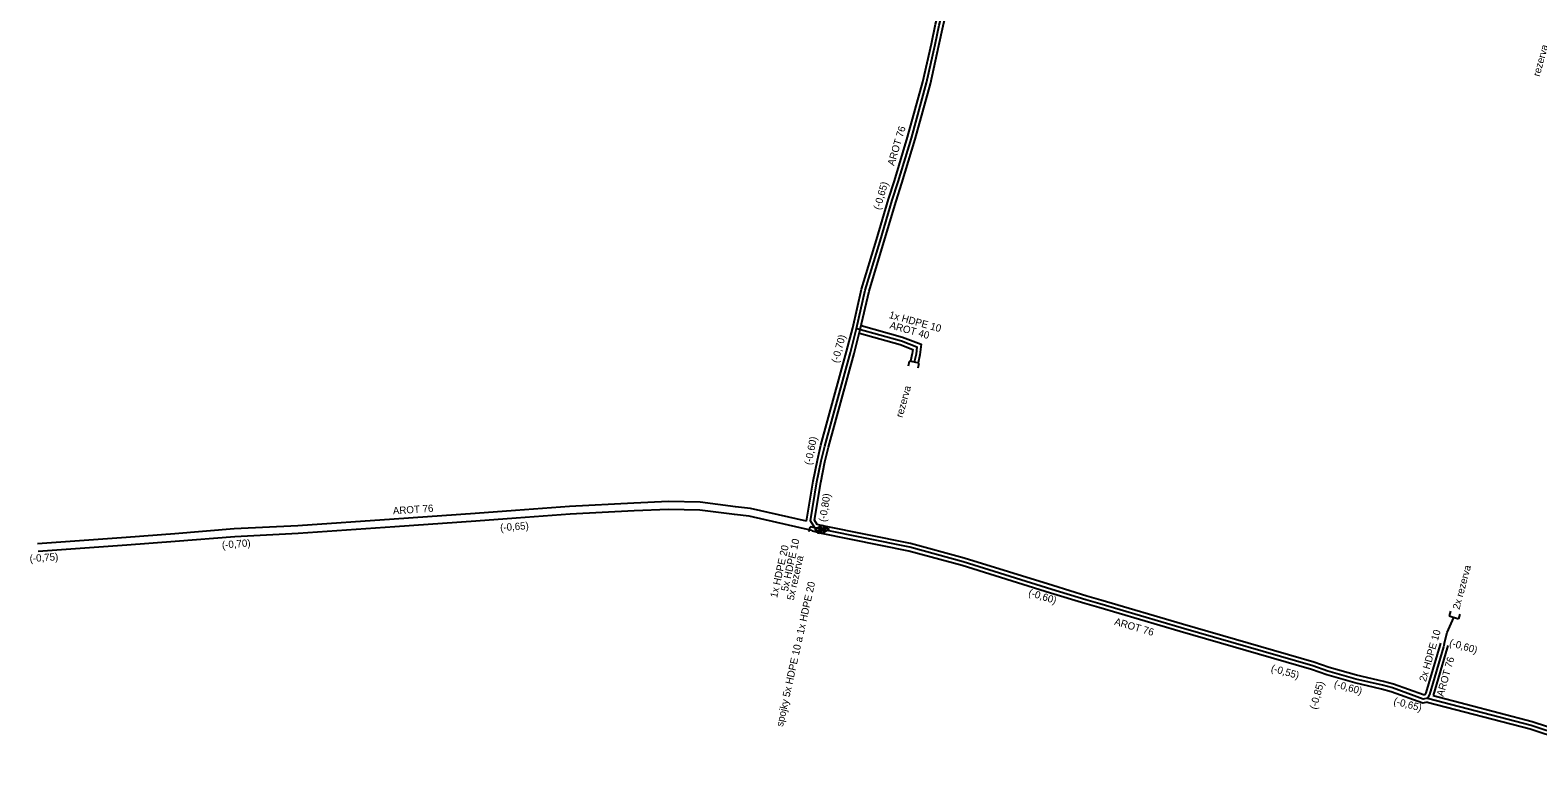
# Model space of a CAD drawing. Extents: x -651943 to -618711, y -1138561 to -1100552.
# Drawn here: x -635177.4 to -635021.9, y -1115478.4 to -1115401.6 of the extents above; entities that cross this region are included whole.
import ezdxf

# ---------------------------------------------------------------- set-up
doc = ezdxf.new("R2010")
doc.units = 0
for name, color, linetype in [('KT optika', 7, 'Continuous'), ('KT trasa', 7, 'Continuous'), ('KT zařízení', 7, 'Continuous')]:
    doc.layers.add(name, color=color, linetype=linetype)

# ---------------------------------------------------------------- blocks, each defined once
blk = doc.blocks.new('TVSPO_1')
at = {"layer": 'KT zařízení'}
for p, q in [((-0.074, 0.002), (0, 0.044)), ((-0.001, -0.041), (-0.074, 0.002)), ((-0.035, 0), (0, 0.02)), ((0.073, 0.001), (-0.001, -0.041)), ((0, 0.044), (0.073, 0.001)), ((0, 0.02), (0.035, 0)), ((0.035, 0), (0, -0.02)), ((0, -0.02), (-0.035, 0))]:
    blk.add_line(p, q, dxfattribs=at)
blk = doc.blocks.new('TVREZ')
at = {"layer": 'KT zařízení'}
for p, q in [((-0.05, 0.05), (0, 0.05)), ((0, -0.05), (0, 0.05)), ((-0.05, -0.05), (0, -0.05))]:
    blk.add_line(p, q, dxfattribs=at)

msp = doc.modelspace()

# ---------------------------------------------------------------- linework, layer by layer
at = {"layer": 'KT optika'}
for points in [[(-635096.92, -1115452.23), (-635096.27, -1115448.2), (-635095.83, -1115446.04), (-635095.46, -1115444.52), (-635092.82, -1115434.86), (-635092.18, -1115432.4), (-635091.28, -1115428.45), (-635089.75, -1115423.38), (-635088.5, -1115419.16), (-635087.89, -1115417.28), (-635086.53, -1115412.77), (-635084.96, -1115407.07), (-635084.08, -1115403.13), (-635083.65, -1115401.11), (-635083.25, -1115399.55), (-635082.29, -1115396.3), (-635082.04, -1115395.65), (-635081.23, -1115392.99), (-635079.5, -1115386.84), (-635079.42, -1115385.67), (-635078.97, -1115383.87), (-635077.85, -1115380.09)], [(-635092.18, -1115432.4), (-635092.03, -1115432.41), (-635087.56, -1115433.65), (-635085.96, -1115434.28), (-635086.04, -1115435.04), (-635086.23, -1115435.85)], [(-635031.6, -1115464.94), (-635031.68, -1115465.2), (-635033.11, -1115470.12), (-635033.33, -1115470.49), (-635033.77, -1115470.59), (-635036.93, -1115469.45), (-635037.96, -1115469.17), (-635040.72, -1115468.53), (-635043.58, -1115467.73), (-635045.15, -1115467.18), (-635058.7, -1115463.25), (-635067.1, -1115460.78), (-635068.54, -1115460.37), (-635072.06, -1115459.28), (-635081.19, -1115456.43), (-635086.7, -1115454.95), (-635095.73, -1115453.12), (-635096.48, -1115452.95), (-635096.92, -1115452.23)], [(-635031.6, -1115464.94), (-635031.29, -1115463.74), (-635030.61, -1115462.17)], [(-635033.33, -1115470.49), (-635022.63, -1115473.28), (-635012.93, -1115476.46), (-635007.19, -1115478.02), (-635006.94, -1115477.98), (-635006.59, -1115477.22), (-635005.3, -1115473.3), (-635005.1, -1115472.7)]]:
    msp.add_lwpolyline(points, dxfattribs=at)
at = {"layer": 'KT trasa'}
for points in [[(-635096.92, -1115452.23), (-635096.27, -1115448.2), (-635095.83, -1115446.04), (-635095.46, -1115444.52), (-635092.82, -1115434.86), (-635092.18, -1115432.4), (-635091.28, -1115428.45), (-635089.75, -1115423.38), (-635088.5, -1115419.16), (-635087.89, -1115417.28), (-635086.53, -1115412.77), (-635084.96, -1115407.07), (-635084.08, -1115403.13), (-635083.65, -1115401.11), (-635083.25, -1115399.55), (-635082.29, -1115396.3), (-635082.04, -1115395.65), (-635081.23, -1115392.99), (-635079.5, -1115386.84), (-635079.42, -1115385.67), (-635078.97, -1115383.87), (-635077.85, -1115380.09)], [(-635092.18, -1115432.4), (-635092.03, -1115432.41), (-635087.56, -1115433.65), (-635085.96, -1115434.28), (-635086.04, -1115435.04), (-635086.23, -1115435.85)], [(-635031.6, -1115464.94), (-635031.68, -1115465.2), (-635033.11, -1115470.12), (-635033.33, -1115470.49), (-635033.77, -1115470.59), (-635036.93, -1115469.45), (-635037.96, -1115469.17), (-635040.72, -1115468.53), (-635043.58, -1115467.73), (-635045.15, -1115467.18), (-635058.7, -1115463.25), (-635067.1, -1115460.78), (-635068.54, -1115460.37), (-635072.06, -1115459.28), (-635081.19, -1115456.43), (-635086.7, -1115454.95), (-635095.73, -1115453.12), (-635096.48, -1115452.95), (-635096.92, -1115452.23)], [(-635031.6, -1115464.94), (-635031.29, -1115463.74), (-635030.61, -1115462.17)], [(-635033.33, -1115470.49), (-635022.63, -1115473.28), (-635012.93, -1115476.46), (-635007.19, -1115478.02), (-635006.94, -1115477.98), (-635006.59, -1115477.22), (-635005.3, -1115473.3), (-635005.1, -1115472.7)]]:
    msp.add_lwpolyline(points, dxfattribs=at)
at = {"layer": 'KT zařízení'}
msp.add_line((-635095.52, -1115453.15), (-635095.73, -1115453.12), dxfattribs=at)
for points in [[(-635097.33, -1115452.27), (-635096.66, -1115448.13), (-635096.22, -1115445.95), (-635095.85, -1115444.42), (-635093.21, -1115434.76), (-635092.57, -1115432.31), (-635091.67, -1115428.35), (-635090.13, -1115423.26), (-635088.88, -1115419.05), (-635088.27, -1115417.16), (-635086.92, -1115412.66), (-635085.35, -1115406.97), (-635084.47, -1115403.05), (-635084.04, -1115401.02), (-635083.63, -1115399.45), (-635082.67, -1115396.17), (-635082.42, -1115395.52), (-635081.61, -1115392.88), (-635079.9, -1115386.77), (-635079.82, -1115385.6), (-635079.36, -1115383.77), (-635078.35, -1115380.38)], [(-635096.5, -1115452.15), (-635095.88, -1115448.27), (-635095.44, -1115446.13), (-635095.07, -1115444.62), (-635092.44, -1115434.97), (-635091.8, -1115432.5), (-635090.89, -1115428.55), (-635089.37, -1115423.49), (-635088.11, -1115419.28), (-635087.51, -1115417.4), (-635086.15, -1115412.88), (-635084.57, -1115407.16), (-635083.69, -1115403.22), (-635083.26, -1115401.2), (-635082.86, -1115399.66), (-635081.91, -1115396.42), (-635081.66, -1115395.78), (-635080.84, -1115393.1), (-635079.11, -1115386.91), (-635079.03, -1115385.73), (-635078.58, -1115383.98), (-635077.47, -1115380.22)], [(-635091.89, -1115432.86), (-635087.69, -1115434.03), (-635086.39, -1115434.54), (-635086.44, -1115434.97), (-635086.62, -1115435.76)], [(-635091.7, -1115432.09), (-635087.43, -1115433.27), (-635085.53, -1115434.02), (-635085.65, -1115435.11), (-635085.84, -1115435.94)], [(-635097.33, -1115452.27), (-635103.1, -1115450.95), (-635104.65, -1115450.78), (-635108.29, -1115450.31), (-635111.58, -1115450.24), (-635115.15, -1115450.4), (-635121.76, -1115450.74), (-635127.33, -1115451.15), (-635131.5, -1115451.45), (-635139.84, -1115452.05), (-635149.78, -1115452.72), (-635156.35, -1115453.06), (-635162.48, -1115453.55), (-635167.49, -1115453.94), (-635176.63, -1115454.58)], [(-635096.79, -1115453.21), (-635103.24, -1115451.74), (-635104.75, -1115451.58), (-635108.35, -1115451.11), (-635111.57, -1115451.04), (-635115.12, -1115451.2), (-635121.71, -1115451.54), (-635127.27, -1115451.94), (-635131.44, -1115452.25), (-635139.78, -1115452.85), (-635149.74, -1115453.52), (-635156.29, -1115453.86), (-635162.42, -1115454.35), (-635167.43, -1115454.74), (-635176.57, -1115455.38)], [(-635033.34, -1115470.9), (-635033.8, -1115471.01), (-635037.05, -1115469.83), (-635038.06, -1115469.56), (-635040.82, -1115468.92), (-635043.7, -1115468.11), (-635045.27, -1115467.56), (-635058.81, -1115463.63), (-635067.21, -1115461.16), (-635068.65, -1115460.75), (-635072.18, -1115459.66), (-635081.3, -1115456.81), (-635086.79, -1115455.34), (-635095.81, -1115453.51), (-635096.73, -1115453.3), (-635096.79, -1115453.21)], [(-635031.98, -1115464.82), (-635032.06, -1115465.08), (-635033.48, -1115469.96), (-635033.59, -1115470.14), (-635033.74, -1115470.17), (-635036.81, -1115469.07), (-635037.86, -1115468.78), (-635040.62, -1115468.14), (-635043.46, -1115467.35), (-635045.03, -1115466.8), (-635058.59, -1115462.87), (-635066.99, -1115460.4), (-635068.43, -1115459.99), (-635071.94, -1115458.9), (-635081.08, -1115456.05), (-635086.61, -1115454.56), (-635095.65, -1115452.73), (-635096.23, -1115452.6), (-635096.5, -1115452.15)], [(-635031.22, -1115465.06), (-635031.3, -1115465.31), (-635032.73, -1115470.23)], [(-635032.73, -1115470.23), (-635022.52, -1115472.9), (-635012.82, -1115476.08), (-635007.21, -1115477.6), (-635006.96, -1115477.07), (-635005.68, -1115473.17), (-635005.48, -1115472.57)], [(-635033.34, -1115470.9), (-635022.74, -1115473.66), (-635013.05, -1115476.84), (-635007.31, -1115478.4)]]:
    msp.add_lwpolyline(points, dxfattribs=at)

# ---------------------------------------------------------------- block references
for p, xscale, yscale, rotation in [((-635086.23, -1115435.85), 9.999989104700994, 9.999989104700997, 78.294855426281), ((-635096.48, -1115452.95), 10.00002132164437, 10.000021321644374, 77.39068404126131), ((-635030.61, -1115462.17), 9.99999500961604, 9.99999500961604, -106.8298317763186)]:
    msp.add_blockref('TVREZ', p, dxfattribs=dict(at, xscale=xscale, yscale=yscale, rotation=rotation))
at = {"layer": 'KT zařízení', "xscale": 10, "yscale": 10}
msp.add_blockref('TVSPO_1', (-635095.73, -1115453.12), dxfattribs=at)

# ---------------------------------------------------------------- texts
at = {"layer": 'KT zařízení'}
for s, rotation, p in [('rezerva', 74.495, (-635021.76, -1115406.47)), ('AROT 76', 73.232, (-635088.31, -1115415.67)), ('(-0,65)', 73.4554, (-635089.75, -1115420.22)), ('1x HDPE 10', 344.4953, (-635088.89, -1115431.3)), ('AROT 40', 344.4953, (-635088.82, -1115432.37)), ('(-0,70)', 74.7353, (-635094.07, -1115436)), ('rezerva', 74.3688, (-635087.45, -1115441.63)), ('(-0,60)', 78.4623, (-635096.84, -1115446.51)), ('(-0,80)', 80.84, (-635095.34, -1115452.37)), ('AROT 76', 3.8538, (-635139.96, -1115451.56)), ('(-0,65)', 4.1823, (-635128.9, -1115453.29)), ('(-0,70)', 4.5739, (-635157.58, -1115455.08)), ('1x HDPE 20', 77.4091, (-635100.37, -1115460.2)), ('5x HDPE 10', 77.4091, (-635099.26, -1115459.54)), ('(-0,75)', 4.005, (-635177.41, -1115456.48)), ('5x rezerva', 77.4091, (-635098.66, -1115460.46)), ('2x rezerva', 74.9209, (-635030.03, -1115461.42)), ('spojky 5x HDPE 10 a 1x HDPE 20', 77.4091, (-635099.77, -1115473.48)), ('(-0,60)', 342.6628, (-635074.52, -1115459.92)), ('AROT 76', 343.616, (-635065.66, -1115462.91)), ('2x HDPE 10', 73.7895, (-635033.48, -1115468.86)), ('(-0,60)', 343.8037, (-635031.13, -1115465.09)), ('(-0,55)', 344.0546, (-635049.51, -1115467.72)), ('AROT 76', 73.7935, (-635031.69, -1115470.38)), ('(-0,85)', 74.0546, (-635044.77, -1115471.71)), ('(-0,60)', 344.0546, (-635043.01, -1115469.33)), ('(-0,65)', 345.3855, (-635036.87, -1115471.12))]:
    msp.add_text(s, height=0.75, rotation=rotation, dxfattribs=at).set_placement(p)

doc.saveas('drawing.dxf')
